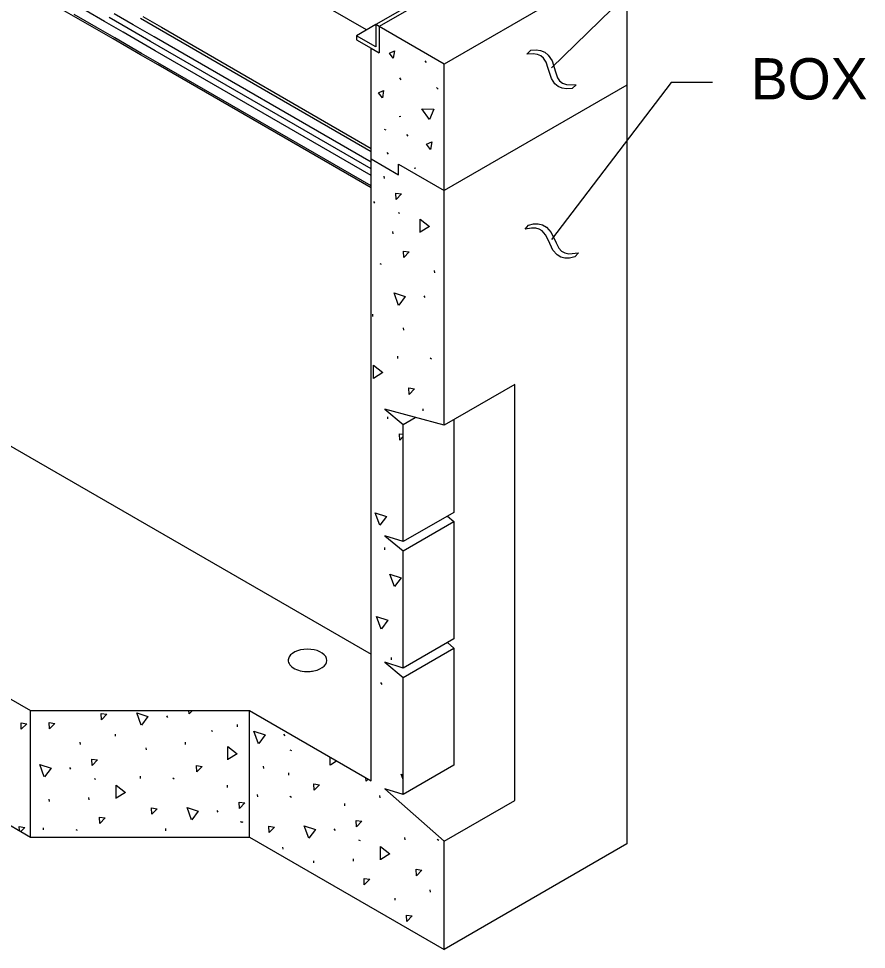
# Model space of a CAD drawing. Extents: x 99862 to 103151, y 100000 to 105076.
# Drawn here: x 101403.4 to 101731.7, y 101072.2 to 101432.8 of the extents above; entities that cross this region are included whole.
import ezdxf

# ---------------------------------------------------------------- set-up
doc = ezdxf.new("R2010")
doc.units = 0
for name, color, linetype in [('Level 11', 7, 'Continuous'), ('Level 15', 7, 'Continuous'), ('Level 2', 7, 'Continuous'), ('Level 20', 7, 'Continuous'), ('Level 3', 7, 'Continuous'), ('Level 4', 7, 'Continuous'), ('Level 9', 7, 'Continuous')]:
    doc.layers.add(name, color=color, linetype=linetype)

msp = doc.modelspace()

# ---------------------------------------------------------------- linework, layer by layer
at = {"layer": 'Level 11'}
for p, q in [((101436.57, 101431.72), (101429.53, 101435.78)), ((101447.67, 101430.41), (101440.34, 101434.65)), ((101433.41, 101429.46), (101424.92, 101434.36)), ((101443.81, 101427.54), (101436.57, 101431.72)), ((101445.76, 101428.96), (101438.48, 101433.17)), ((101457.98, 101428.54), (101450.61, 101432.8)), ((101440.59, 101425.32), (101433.41, 101429.46)), ((101453.14, 101422.15), (101443.81, 101427.54)), ((101454.5, 101423.92), (101445.76, 101428.96)), ((101455.85, 101425.69), (101447.67, 101430.41)), ((101539.92, 101381.24), (101457.98, 101428.54)), ((101450.93, 101419.34), (101440.59, 101425.32)), ((101539.92, 101374.6), (101454.5, 101423.92)), ((101539.92, 101377.15), (101455.85, 101425.69)), ((101456.3, 101420.33), (101453.14, 101422.15)), ((101539.92, 101372.05), (101456.3, 101420.33)), ((101457.24, 101415.7), (101450.93, 101419.34)), ((101539.92, 101367.97), (101457.24, 101415.7))]:
    msp.add_line(p, q, dxfattribs=at)
at = {"layer": 'Level 15'}
for p, q in [((101656.12, 101459.01), (101609.73, 101413.76)), ((101600.23, 101419.09), (101601.77, 101420.53)), ((101601.77, 101420.53), (101603.75, 101420.73)), ((101603.75, 101420.73), (101605.53, 101420.49)), ((101605.53, 101420.49), (101607.09, 101419.82)), ((101602.66, 101419.12), (101600.23, 101419.09)), ((101604.37, 101418.88), (101602.66, 101419.12)), ((101605.63, 101418.35), (101604.37, 101418.88)), ((101606.67, 101417.51), (101605.63, 101418.35)), ((101607.69, 101415.89), (101606.67, 101417.51)), ((101607.09, 101419.82), (101608.45, 101418.7)), ((101608.45, 101418.7), (101609.94, 101416.42)), ((101608.49, 101413.47), (101607.69, 101415.89)), ((101609.67, 101409.55), (101608.49, 101413.47)), ((101609.94, 101416.42), (101611.3, 101412.22)), ((101611.07, 101407.52), (101609.67, 101409.55)), ((101611.3, 101412.22), (101612.05, 101409.91)), ((101612.05, 101409.91), (101612.88, 101408.67)), ((101656.12, 101407.99), (101609.73, 101347.28)), ((101612.34, 101406.45), (101611.07, 101407.52)), ((101613.83, 101405.82), (101612.34, 101406.45)), ((101612.88, 101408.67), (101614.02, 101407.82)), ((101615.59, 101405.57), (101613.83, 101405.82)), ((101614.02, 101407.82), (101615.58, 101407.29)), ((101615.58, 101407.29), (101619.28, 101407.14)), ((101617.73, 101405.7), (101615.59, 101405.57)), ((101619.28, 101407.14), (101617.73, 101405.7)), ((101672.12, 101407.99), (101656.12, 101407.99)), ((101599.56, 101351.18), (101600.88, 101352.83)), ((101601.95, 101351.57), (101599.56, 101351.18)), ((101600.88, 101352.84), (101602.81, 101353.32)), ((101603.69, 101351.58), (101601.95, 101351.57)), ((101602.81, 101353.32), (101604.6, 101353.34)), ((101605, 101351.23), (101603.69, 101351.58)), ((101604.6, 101353.34), (101606.24, 101352.9)), ((101606.24, 101352.9), (101607.75, 101351.99)), ((101607.75, 101351.99), (101609.55, 101349.95)), ((101606.15, 101350.56), (101605, 101351.23)), ((101607.41, 101349.1), (101606.15, 101350.56)), ((101608.54, 101346.82), (101607.41, 101349.1)), ((101609.55, 101349.95), (101611.51, 101345.99)), ((101610.28, 101343.12), (101608.54, 101346.82)), ((101611.51, 101345.99), (101612.58, 101343.82)), ((101611.96, 101341.3), (101610.28, 101343.12)), ((101613.37, 101340.44), (101611.96, 101341.3)), ((101612.58, 101343.82), (101613.59, 101342.71)), ((101613.59, 101342.71), (101614.84, 101342.03)), ((101614.84, 101342.03), (101616.46, 101341.73)), ((101616.46, 101341.73), (101620.13, 101342.12)), ((101620.13, 101342.12), (101618.82, 101340.47)), ((101614.94, 101340.02), (101613.37, 101340.44)), ((101616.71, 101340.03), (101614.94, 101340.02)), ((101618.82, 101340.47), (101616.71, 101340.03))]:
    msp.add_line(p, q, dxfattribs=at)
at = {"layer": 'Level 2'}
for p, q in [((101432.8, 101429.05), (101404.46, 101445.41)), ((101451.51, 101433.56), (101458.65, 101429.43)), ((101439.97, 101424.91), (101432.8, 101429.05)), ((101458.65, 101429.43), (101539.92, 101382.51)), ((101450.51, 101418.82), (101439.97, 101424.91)), ((101457.41, 101414.84), (101450.51, 101418.82)), ((101539.92, 101367.2), (101457.41, 101414.84)), ((101638.91, 101407.01), (101568.2, 101366.18)), ((101638.91, 101407.01), (101638.91, 101113.07)), ((101539.92, 101378.43), (101550.52, 101372.31)), ((101539.92, 101137.56), (101539.92, 101378.43)), ((101550.52, 101372.31), (101550.52, 101376.39)), ((101550.52, 101376.39), (101568.2, 101366.18)), ((101568.2, 101275.31), (101568.2, 101366.18)), ((101330.27, 101307.59), (101539.92, 101186.55)), ((101595.57, 101291.12), (101568.2, 101275.31)), ((101595.57, 101167.37), (101595.57, 101291.12)), ((101545.22, 101281.47), (101552.29, 101275.6)), ((101568.2, 101275.31), (101545.22, 101281.47)), ((101552.29, 101275.6), (101556.99, 101278.32)), ((101571.96, 101277.48), (101571.96, 101241.54)), ((101552.29, 101230.19), (101552.29, 101275.6)), ((101571.96, 101241.54), (101552.29, 101230.19)), ((101569.42, 101240.07), (101571.96, 101237.96)), ((101552.29, 101226.61), (101571.96, 101237.96)), ((101571.96, 101237.96), (101571.96, 101192.55)), ((101552.29, 101230.19), (101545.22, 101232.48)), ((101545.22, 101232.48), (101552.29, 101226.61)), ((101552.29, 101192.36), (101552.29, 101226.61)), ((101571.96, 101192.55), (101552.29, 101181.2)), ((101552.29, 101181.2), (101552.29, 101192.36)), ((101569.42, 101191.08), (101571.96, 101188.97)), ((101552.29, 101177.62), (101571.96, 101188.97)), ((101571.96, 101188.97), (101571.96, 101143.56)), ((101552.29, 101181.2), (101545.22, 101183.49)), ((101545.22, 101183.49), (101552.29, 101177.62)), ((101552.29, 101132.21), (101552.29, 101177.62)), ((101391.42, 101174.31), (101407.97, 101164.76)), ((101407.97, 101164.76), (101492.82, 101164.76)), ((101407.97, 101115.77), (101407.97, 101164.76)), ((101492.82, 101164.76), (101539.92, 101137.56)), ((101492.82, 101115.77), (101492.82, 101164.76)), ((101595.57, 101129.93), (101595.57, 101167.37)), ((101571.96, 101143.56), (101552.29, 101132.21)), ((101377.28, 101133.48), (101407.97, 101115.77)), ((101552.29, 101132.21), (101545.22, 101134.5)), ((101545.22, 101134.5), (101568.2, 101114.12)), ((101568.2, 101114.12), (101595.57, 101129.93)), ((101407.97, 101115.77), (101492.82, 101115.77)), ((101492.82, 101115.77), (101568.2, 101072.24)), ((101568.2, 101072.24), (101568.2, 101114.12)), ((101638.91, 101113.07), (101568.2, 101072.24))]:
    msp.add_line(p, q, dxfattribs=at)
for start_param, end_param in [(1.905093, 6.135148), (6.135148, 7.915253), (1.632068, 1.905093)]:
    msp.add_ellipse((101515.26, 101184.2), major_axis=(-7.5, 0), ratio=0.57735, start_param=start_param, end_param=end_param, dxfattribs=at)
at = {"layer": 'Level 3'}
for p, q in [((101538.15, 101428.44), (101477.09, 101463.69)), ((101586.32, 101454.72), (101543.01, 101429.72)), ((101638.91, 101456), (101568.2, 101415.17)), ((101638.91, 101456), (101638.91, 101407.01)), ((101568.2, 101415.17), (101543.01, 101429.72)), ((101539.92, 101378.43), (101539.92, 101421.3)), ((101568.2, 101366.18), (101568.2, 101415.17))]:
    msp.add_line(p, q, dxfattribs=at)
at = {"layer": 'Level 4'}
for p, q in [((101583.67, 101454.72), (101541.68, 101430.48)), ((101541.68, 101430.48), (101534.17, 101426.14)), ((101541.68, 101430.48), (101541.68, 101421.81)), ((101543.01, 101429.72), (101541.68, 101430.48)), ((101543.01, 101429.72), (101543.01, 101419.51)), ((101534.17, 101426.14), (101534.17, 101424.61)), ((101541.68, 101421.81), (101534.17, 101426.14)), ((101534.17, 101424.61), (101539.92, 101421.3)), ((101539.92, 101421.3), (101543.01, 101419.51))]:
    msp.add_line(p, q, dxfattribs=at)
at = {"layer": 'Level 9'}
for p, q in [((101561.38, 101415.79), (101560.83, 101416.47)), ((101551.51, 101409.14), (101550.96, 101409.82)), ((101565.8, 101405.47), (101565.25, 101406.15)), ((101550.73, 101394.9), (101551.37, 101394.98)), ((101544.89, 101389.94), (101545.64, 101389.66)), ((101554.22, 101387.25), (101553.67, 101387.93)), ((101546.6, 101380.31), (101546.05, 101380.99)), ((101556.59, 101374.88), (101557.22, 101374.95)), ((101545.02, 101370.92), (101544.96, 101371.79)), ((101540.78, 101362.01), (101541.23, 101361.35)), ((101550.32, 101357.72), (101550.89, 101357.42)), ((101548.38, 101349.46), (101548.32, 101350.33)), ((101543.22, 101337.97), (101543.79, 101337.67)), ((101564.49, 101334.29), (101564.43, 101335.16)), ((101560.25, 101325.39), (101560.7, 101324.72)), ((101540.56, 101317.44), (101540.5, 101318.32)), ((101552.53, 101312.14), (101552.47, 101313.01)), ((101550.23, 101301.15), (101550.17, 101302.02)), ((101562.7, 101301.34), (101563.26, 101301.04)), ((101560.04, 101280.82), (101559.97, 101281.69)), ((101546.41, 101277.7), (101546.35, 101278.57)), ((101545.24, 101227), (101545.18, 101227.87)), ((101547.8, 101184.47), (101547.74, 101185.35)), ((101543.56, 101175.57), (101544.01, 101174.9)), ((101540.07, 101173.88), (101540.07, 101173.88)), ((101460.6, 101162.72), (101461.06, 101162.06)), ((101477.89, 101157.04), (101478.46, 101156.73)), ((101488.14, 101158.45), (101488.08, 101159.33)), ((101440.92, 101154.78), (101440.85, 101155.65)), ((101506, 101155.6), (101506.45, 101154.93)), ((101427.29, 101151.65), (101427.23, 101152.53)), ((101452.89, 101149.48), (101452.83, 101150.35)), ((101468, 101151.62), (101467.94, 101152.5)), ((101508.45, 101149.6), (101509.02, 101149.29)), ((101423.05, 101142.75), (101423.5, 101142.09)), ((101498.28, 101142.35), (101498.22, 101143.23)), ((101450.58, 101138.48), (101450.52, 101139.36)), ((101508.07, 101139.72), (101508, 101140.59)), ((101432.6, 101138.46), (101433.16, 101138.15)), ((101463.05, 101138.68), (101463.62, 101138.37)), ((101484.32, 101135), (101484.26, 101135.87)), ((101495.98, 101131.36), (101495.92, 101132.23)), ((101543.34, 101131), (101543.28, 101131.87)), ((101415.33, 101129.51), (101415.27, 101130.38)), ((101430.65, 101130.2), (101430.59, 101131.07)), ((101508.45, 101131.55), (101509.01, 101131.25)), ((101529.71, 101127.88), (101529.65, 101128.75)), ((101480.08, 101126.09), (101480.53, 101125.43)), ((101489.22, 101121.81), (101489.78, 101121.51)), ((101489.63, 101121.8), (101490.19, 101121.5)), ((101413.03, 101118.51), (101412.96, 101119.39)), ((101425.5, 101118.71), (101426.06, 101118.4)), ((101460.39, 101118.15), (101460.33, 101119.02)), ((101525.47, 101118.97), (101525.93, 101118.31)), ((101446.71, 101115.77), (101446.7, 101115.9)), ((101535.02, 101114.68), (101535.58, 101114.38)), ((101553.01, 101114.71), (101552.95, 101115.58)), ((101565.48, 101114.9), (101566.04, 101114.59)), ((101505.78, 101111.03), (101505.72, 101111.9)), ((101517.75, 101105.73), (101517.69, 101106.6)), ((101533.08, 101106.42), (101533.01, 101107.29)), ((101549.19, 101091.25), (101549.13, 101092.12)), ((101562.82, 101094.37), (101562.75, 101095.25))]:
    msp.add_line(p, q, dxfattribs=at)
for points in [[(101546.97, 101419.38), (101548.96, 101420.35), (101548.46, 101417.42)], [(101548.46, 101417.42), (101546.97, 101419.38)], [(101544.23, 101402.06), (101542.73, 101404.02), (101544.73, 101405), (101544.23, 101402.06)], [(101562.49, 101393.7), (101559.54, 101397.89), (101564.11, 101397.66), (101562.53, 101393.78)], [(101562.88, 101382.14), (101561.38, 101384.1), (101563.38, 101385.07), (101562.88, 101382.14)], [(101549.55, 101362.77), (101549.45, 101365.23), (101551.64, 101364.89), (101549.55, 101362.77)], [(101558.85, 101350), (101558.85, 101355.13), (101562.45, 101352.32), (101558.93, 101350.04)], [(101552.54, 101340.31), (101552.44, 101342.77), (101554.63, 101342.43), (101552.54, 101340.31)], [(101550.53, 101321.7), (101548.77, 101326.52), (101553.12, 101325.11), (101550.59, 101321.77)], [(101540.77, 101293.4), (101540.76, 101298.53), (101544.37, 101295.72), (101540.85, 101293.45)], [(101554.63, 101287.25), (101554.52, 101289.71), (101556.72, 101289.36), (101554.63, 101287.25)], [(101550.94, 101269.55), (101550.84, 101272.01), (101552.29, 101271.78)], [(101552.29, 101270.91), (101550.94, 101269.55)], [(101543.24, 101236.56), (101541.48, 101241.37), (101545.83, 101239.97), (101543.3, 101236.63)], [(101548.89, 101212.77), (101547.13, 101217.58), (101551.48, 101216.17), (101548.95, 101212.83)], [(101543.78, 101196.35), (101542.02, 101201.16), (101546.37, 101199.75), (101543.84, 101196.41)], [(101552.29, 101177.35), (101552.28, 101177.63)], [(101469.38, 101163.48), (101469.33, 101164.76)], [(101470.65, 101164.76), (101469.38, 101163.48)], [(101435.51, 101161.21), (101435.4, 101163.67), (101437.6, 101163.32), (101435.51, 101161.21)], [(101450.89, 101159.04), (101449.12, 101163.85), (101453.47, 101162.44), (101450.95, 101159.1)], [(101404.41, 101157.55), (101404.31, 101160.01), (101406.5, 101159.67), (101404.41, 101157.55)], [(101415.34, 101157.67), (101415.24, 101160.13), (101417.43, 101159.79), (101415.34, 101157.67)], [(101496.28, 101151.92), (101494.52, 101156.73), (101498.87, 101155.32), (101496.34, 101151.98)], [(101484.37, 101145.7), (101484.36, 101150.82), (101487.97, 101148.01), (101484.45, 101145.74)], [(101524.08, 101143.59), (101524.07, 101146.71)], [(101413.33, 101139.07), (101411.57, 101143.88), (101415.92, 101142.47), (101413.39, 101139.13)], [(101431.82, 101143.51), (101431.72, 101145.97), (101433.91, 101145.62), (101431.82, 101143.51)], [(101472.37, 101141.01), (101472.27, 101143.48), (101474.46, 101143.13), (101472.37, 101141.01)], [(101526.64, 101145.23), (101524.16, 101143.63)], [(101552.29, 101138.05), (101551.55, 101140.07), (101552.29, 101139.83)], [(101441.13, 101130.74), (101441.12, 101135.86), (101444.72, 101133.05), (101441.2, 101130.78)], [(101517.76, 101133.89), (101517.66, 101136.35), (101519.86, 101136.01), (101517.76, 101133.89)], [(101537.93, 101137.43), (101537.88, 101138.74)], [(101538.74, 101138.24), (101537.93, 101137.43)], [(101488.86, 101126.85), (101488.75, 101129.31), (101490.95, 101128.97), (101488.86, 101126.85)], [(101454.98, 101124.58), (101454.88, 101127.04), (101457.07, 101126.7), (101454.98, 101124.58)], [(101470.36, 101122.41), (101468.6, 101127.22), (101472.95, 101125.82), (101470.42, 101122.48)], [(101434.81, 101121.04), (101434.71, 101123.51), (101436.9, 101123.16), (101434.81, 101121.04)], [(101534.25, 101119.73), (101534.15, 101122.19), (101536.34, 101121.85), (101534.25, 101119.73)], [(101403.68, 101118.24), (101403.62, 101119.85), (101405.81, 101119.5), (101404.24, 101117.92)], [(101500.37, 101117.46), (101500.27, 101119.92), (101502.47, 101119.58), (101500.37, 101117.46)], [(101515.75, 101115.29), (101513.99, 101120.1), (101518.34, 101118.69), (101515.81, 101115.36)], [(101543.55, 101106.96), (101543.54, 101112.08), (101547.15, 101109.28), (101543.63, 101107)], [(101557.41, 101100.8), (101557.3, 101103.26), (101559.5, 101102.92), (101557.41, 101100.8)], [(101537.24, 101097.27), (101537.14, 101099.73), (101539.33, 101099.39), (101537.24, 101097.27)], [(101553.72, 101083.1), (101553.62, 101085.56), (101555.82, 101085.22), (101553.72, 101083.1)]]:
    msp.add_lwpolyline(points, dxfattribs=at)

# ---------------------------------------------------------------- texts
at = {"layer": 'Level 20'}
msp.add_text('BOX', height=16, dxfattribs=at).set_placement((101686.93, 101401.48))

doc.saveas('drawing.dxf')
